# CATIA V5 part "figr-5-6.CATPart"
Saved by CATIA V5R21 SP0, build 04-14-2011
Part number: Part1
Bounding box of the stored display mesh (mm): x 0 to 150, y -70 to 70, z -150 to 69.804
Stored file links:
  D:\CATIA V5R21 E-RESOURCES\CATIA-V5R21\catia-v5r21-prt\c05-catia-v5r20-prt\catia-v5r21-figr-5-6.CATPart
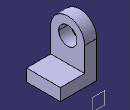
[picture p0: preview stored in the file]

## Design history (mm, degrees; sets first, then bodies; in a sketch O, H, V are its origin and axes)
Set1
  Plane1: type Offset, RefPlane face of Pad2, Offset 79, reversed
Body1 (main body)
  Sketch1 on yz-plane, origin (0, 0, 0), H (0, 1, 0), V (0, 0, 1)
    arc A1 centre (0, 0) radius 70 from (70, 0) to (-70, 0) ccw
    point P1 (70, 0)
    point P2 (-70, 0)
    line L1 (-70, 0) -> (-70, -150)
    line L2 (-70, -150) -> (70, -150)
    line L3 (70, -150) -> (70, 0)
    circle A2 centre (0, 0) radius 37.5
    radius A1 = 70
    radius A2 = 37.5
    distance O L2 = 150
    coincidence: P1 H, P2 H
    tangency: L1 A1, L3 A1
    horizontal: L2 H
  Pad1: profile Sketch1, direction (1, 0, 0), length 50
  Sketch2 on face of Pad1, origin (50, 0, 0), H (0, 1, 0), V (0, 0, 1)
    line L1 (-70, -150) -> (70, -150)
    line L2 (70, -150) -> (70, -100)
    line L3 (70, -100) -> (-70, -100)
    line L4 (-70, -100) -> (-70, -150)
    reference projected line E1 (-70, -150) -> (70, -150) from edge [face of Pad1 | face of Pad1]
    reference projected line E2 (-70, 0) -> (-70, -150) from edge [face of Pad1 | face of Pad1]
    reference projected line E3 (70, -150) -> (70, 0) from edge [face of Pad1 | face of Pad1]
    length L2 = 50
    horizontal: L1 H, L3 H
    vertical: L2 V, L4 V
    coincidence: L1 E1, E2 L4, L2 E3
  Pad2: profile Sketch2, direction (1, 0, 0), length 100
